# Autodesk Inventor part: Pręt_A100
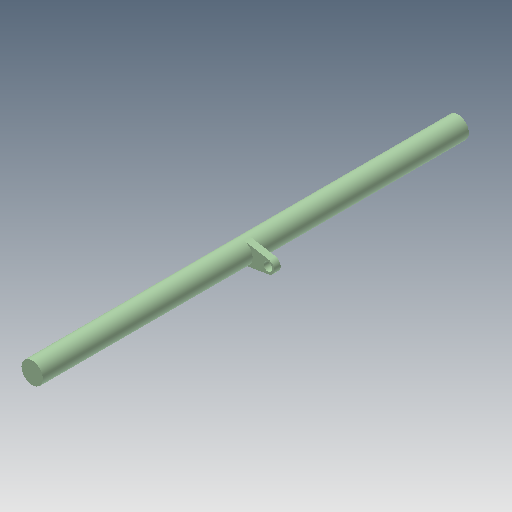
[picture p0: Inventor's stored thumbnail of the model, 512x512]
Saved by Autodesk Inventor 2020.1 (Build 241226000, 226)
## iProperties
Created: 2006-06
Part Number: Pręt_A100
Document SubType Name: Modeling
Designer: F.Stasiak
Density: 1 g/cm^3
Material: Ogólny
Appearance: Zielony pastelowy
Manager: www.cadconsulting.pl
Company: Fabian Stasiak CAD Consulting
Author: F.Stasiak
Subject: Zbiór ćwiczeń. Autodesk Inventor 2020. Kurs podstawowy
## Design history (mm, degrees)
sketch "Szkic1"
  geometry: C1 r 25 at (0, 0); 1 further point
  constraints: 1 centre point, 1 coincident
  dimensions: "d0" = 50 diameter of C1
extrude "Wyciągnięcie proste1" new body sketch "Szkic1" distance "d1" = 990; taper "d2" = 0 deg
node "Płaszczyzna konstrukcyjna1"
sketch "Szkic2"
  geometry: L1 (-62.5, 14.79)-(-4.167, 24.65); L2 (-62.5, -14.79)-(-4.167, -24.65); L3 (-60, 0)-(0, 0); C1 r 10 at (-60, 0); A1 r 25 centre (0, 0) between (-4.167, 24.65) and (-4.167, -24.65) reference; A2 r 15 centre (-60, 0) between (-62.5, 14.79) and (-62.5, -14.79)
  constraints: 6 end point, 4 point on circle, 4 tangent, 2 centre point, 1 coincident, 1 horizontal
  dimensions: "d3" = 30 diameter of A2; "d4" = 60 distance of L3.end L3.start; "d7" = 20 diameter of C1
extrude "Wyciągnięcie proste2" join sketch "Szkic2" stored distance "d8" = 15; taper "d9" = 0 deg
node "Bryła1"
node "Korpusy bryłowe"
node "Korpusy powierzchniowe"
